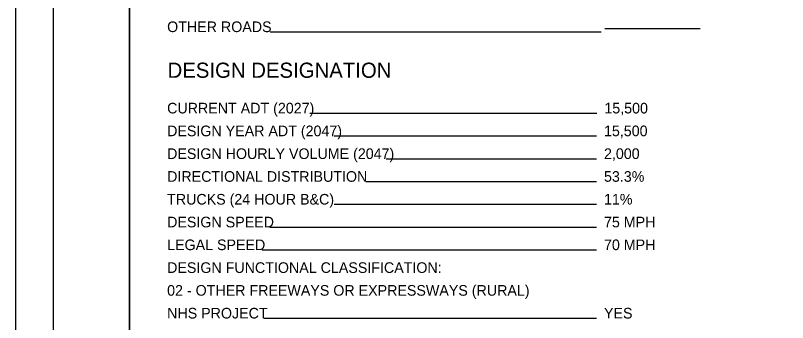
# Model space of a CAD drawing. Extents: x 0 to 36.9, y 0 to 22.
# Drawn here: x 0 to 10.15, y 7.05 to 11.1 of the extents above; entities that cross this region are included whole.
import ezdxf

# ---------------------------------------------------------------- set-up
doc = ezdxf.new("R2010")
doc.units = 0
for name, color, linetype in [('SH_Border', 7, 'Continuous'), ('SH_Cut_Line', 7, 'Continuous'), ('SH_Data', 7, 'Continuous'), ('SH_Text', 7, 'Continuous')]:
    doc.layers.add(name, color=color, linetype=linetype)

msp = doc.modelspace()

# ---------------------------------------------------------------- linework, layer by layer
at = {"layer": 'SH_Border'}
for points in [[(0.5, 21.5), (1.5, 21.5), (1.5, 0.5), (0.5, 0.5)], [(1.5, 21.5), (33.5, 21.5), (33.5, 0.5), (1.5, 0.5)]]:
    msp.add_lwpolyline(points, close=True, dxfattribs=at)
at = {"layer": 'SH_Cut_Line'}
msp.add_lwpolyline([(0, 0), (34, 0), (34, 22), (0, 22)], close=True, dxfattribs=at)
at = {"layer": 'SH_Data'}
for p, q in [((7.7, 10.877), (3.347, 10.877)), ((9, 10.922), (7.75, 10.922)), ((7.642, 9.806), (3.871, 9.806)), ((7.637, 9.506), (4.189, 9.506)), ((7.637, 9.206), (4.872, 9.206)), ((7.637, 8.906), (4.604, 8.906)), ((7.637, 8.606), (4.189, 8.606)), ((7.637, 8.306), (3.346, 8.306)), ((7.637, 8.006), (3.242, 8.006)), ((7.637, 7.106), (3.267, 7.106))]:
    msp.add_line(p, q, dxfattribs=at)

# ---------------------------------------------------------------- texts
msp.add_text('DESIGN DESIGNATION', height=0.2, dxfattribs=at).set_placement((2, 10.275))
at = {"layer": 'SH_Text'}
for s, p in [('OTHER ROADS', (1.994, 10.877)), ('CURRENT ADT (2027)', (1.994, 9.806)), ('15,500', (7.742, 9.806)), ('DESIGN YEAR ADT (2047)', (1.994, 9.506)), ('15,500', (7.737, 9.506)), ('DESIGN HOURLY VOLUME (2047)', (1.994, 9.206)), ('2,000', (7.737, 9.206)), ('DIRECTIONAL DISTRIBUTION', (1.994, 8.906)), ('53.3%', (7.737, 8.906)), ('TRUCKS (24 HOUR B&C)', (1.994, 8.606)), ('11%', (7.737, 8.606)), ('DESIGN SPEED', (1.994, 8.306)), ('75 MPH', (7.737, 8.306)), ('LEGAL SPEED', (1.994, 8.006)), ('70 MPH', (7.737, 8.006)), ('DESIGN FUNCTIONAL CLASSIFICATION:', (1.994, 7.706)), ('02 - OTHER FREEWAYS OR EXPRESSWAYS (RURAL)', (1.994, 7.406)), ('NHS PROJECT', (1.994, 7.106)), ('YES', (7.737, 7.106))]:
    msp.add_text(s, height=0.14, dxfattribs=at).set_placement(p)

doc.saveas('drawing.dxf')
